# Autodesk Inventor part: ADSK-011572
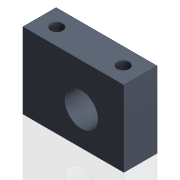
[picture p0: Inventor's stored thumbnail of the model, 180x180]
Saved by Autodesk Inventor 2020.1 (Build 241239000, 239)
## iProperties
Created: 2000-02
Part Number: ADSK-011572
Document SubType Name: Modeling
Designer: sspink
Material: Pearson Nylatron
Density: 1.13867 g/cm^3
Appearance: Nylatron
Mass: 105.998 g
Surface Area: 175.723 cm^2
Volume: 93.0889 cm^3
Control State: 0
Checked Out: False
Master: False
Shininess: 10.0
Length Units: 11269
Angle Units: 11279
Time Units: 11290
Mass Units: 11283
Length Display Precision: 3
Angle Display Precision: 2
Compacted: True
Cutlength: 3.00X2.25 (6.75 SI)
Material Desc: SHEET,NYLATRON,1.00
Material_Number: A092353
Dimensions: 57x25x76 mm
Mass: 0,106 kg
VLT_Material: Pearson Nylatron
Density: 1.13867
Volumn: 93.66093998461692
Area: 181.06483160891167
PropertySet Name: Model Information
Author: sspink
Revision Number: -
Title: ADSK-011572
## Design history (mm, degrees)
node "Extrusion1" dims "d2" = 25, "d3" = 0
  sketch "Sketch1"
    geometry: L1 (0, 0)-(76, 0); L2 (76, 0)-(76, 57); L3 (76, 57)-(0, 57); L4 (0, 57)-(0, 0)
    constraints: 8 end point, 2 parallel, 1 horizontal, 1 perpendicular
    dimensions: "d0" = 57 distance between parallel lines of L1 L3; "d1" = 76 distance between parallel lines of L2 L4
node "Extrusion2" dims "d6" = 25.4, "d7" = 0
  sketch "Sketch2"
    geometry: L1 (76, 57)-(76, 0) reference; L2 (76, 0)-(0, 0) reference; C1 r 12.5 at (44, 25)
    constraints: 1 centre point
    dimensions: "d4" = 25 diameter of C1; "d5" = 32 distance from line of C1.centre L1; "d16" = 25 distance from line of C1.centre L2
node "Hole1" dims "d10" = 9, "d11" = 9.525, "d12" = 6.35, "d13" = 60 deg, "d14" = 22.2, "d15" = 118 deg, "d17" = 16
  sketch "Sketch3"
    geometry: L1 (76, 0)-(76, -25) reference; L2 (13, -12.5)-(63, -12.5); L3 (76, 0)-(0, 0) reference; 3 further points
    constraints: 3 midpoint, 2 end point, 1 horizontal, 1 horizontal alignment, 1 vertical alignment
    dimensions: "d18" = 50 distance of L2.start L2.end
workplane "Arbeitsebene1"
  workaxis "Arbeitsachse1"
node "Solide1"
node "Corps solides"
node "Corps surfaciques"
other parameters: "d19" = 90 deg
